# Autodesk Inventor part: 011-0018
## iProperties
Created: 2007-02
Part Number: 011-0018
Document SubType Name: Modeling
Designer: GG5883
Description: Came de serrage
Stock Number: 11-0018
Material: 34 Cr Mo 4
User Status: GG5883
Author: GG5883
Revision Number: 00
Title: CAME
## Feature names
1. Révolution1 [Revolution]
2. Perçage1 [Hole]
3. Perçage2 [Hole]
4. Chanfrein1 [Chamfer]
5. Découpe AF [Extrusion]
